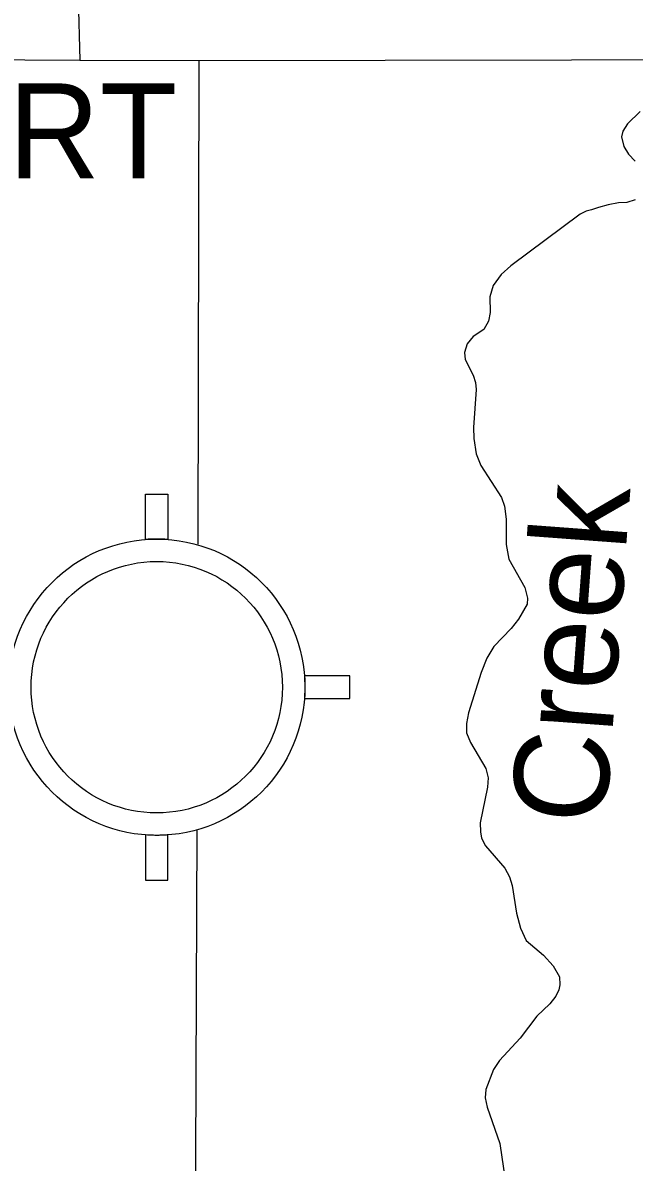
# Model space of a CAD drawing. Extents: x 1377389 to 1380723, y 1168351 to 1170484.
# Drawn here: x 1378669.2 to 1378723.7, y 1169222.9 to 1169324.4 of the extents above; entities that cross this region are included whole.
import ezdxf

# ---------------------------------------------------------------- set-up
doc = ezdxf.new("R2010")
doc.units = 0
doc.layers.add('B_Fill', color=7, linetype='Continuous')

msp = doc.modelspace()

# ---------------------------------------------------------------- linework, layer by layer
at = {"layer": 'B_Fill'}
for p, q in [((1378680.12, 1169278.37), (1378680.12, 1169282.41)), ((1378680.12, 1169282.41), (1378682.12, 1169282.41)), ((1378698.32, 1169266.21), (1378694.28, 1169266.21)), ((1378698.32, 1169264.21), (1378698.32, 1169266.21)), ((1378682.12, 1169248.01), (1378682.12, 1169252.05)), ((1378680.12, 1169248.01), (1378682.12, 1169248.01))]:
    msp.add_line(p, q, dxfattribs=at)
for points in [[(1378673.68, 1169343.19), (1378674.25, 1169321.07)], [(1378580.97, 1169321.62), (1378674.25, 1169321.07), (1378684.86, 1169321.03), (1378718.08, 1169321.08)], [(1378684.86, 1169321.03), (1378684.77, 1169277.94)], [(1378718.08, 1169321.08), (1378766.19, 1169321.15)], [(1378724.21, 1169316.49), (1378723.08, 1169315.4), (1378722.67, 1169314.75), (1378722.54, 1169314.23), (1378722.76, 1169313.37), (1378723.16, 1169312.7), (1378723.75, 1169312.06)], [(1378723.77, 1169308.61), (1378723.01, 1169308.38), (1378722.27, 1169308.34), (1378721.35, 1169308.18), (1378720.49, 1169307.95), (1378719.86, 1169307.74), (1378719.38, 1169307.62), (1378718.86, 1169307.33)], [(1378718.86, 1169307.33), (1378712.68, 1169302.74), (1378711.8, 1169301.98), (1378711.09, 1169300.98), (1378710.81, 1169299.98), (1378710.82, 1169298.58), (1378710.68, 1169297.81), (1378710.26, 1169297.08), (1378709.31, 1169296.44), (1378708.77, 1169295.79), (1378708.55, 1169295.02), (1378708.62, 1169294.4), (1378709.31, 1169293), (1378709.52, 1169292.36), (1378709.6, 1169291.72), (1378709.35, 1169288.35), (1378709.38, 1169287.35), (1378709.59, 1169286)], [(1378709.59, 1169286), (1378709.99, 1169284.97), (1378711.85, 1169282.12), (1378712.11, 1169281.33), (1378712.27, 1169280.19), (1378712.26, 1169277.93), (1378712.51, 1169276.62), (1378713.93, 1169274.08), (1378714.15, 1169273.15), (1378714.12, 1169272.61), (1378713.35, 1169271.27), (1378712.71, 1169270.45), (1378711.17, 1169268.84), (1378710.53, 1169267.8), (1378710.02, 1169266.53), (1378708.89, 1169262.94), (1378708.71, 1169261.98), (1378708.73, 1169261.16), (1378709.09, 1169260.29), (1378710.46, 1169257.97), (1378710.65, 1169257.14), (1378710.61, 1169256.32), (1378709.95, 1169253.12), (1378709.96, 1169252.32), (1378710.06, 1169251.76), (1378710.43, 1169251.09), (1378712.13, 1169249.08), (1378712.57, 1169248.33), (1378712.8, 1169247.56), (1378713.18, 1169245.08), (1378713.55, 1169243.75), (1378714.03, 1169242.66), (1378715.58, 1169241.33), (1378716.46, 1169240.39), (1378717, 1169239.42), (1378717.05, 1169238.7), (1378716.96, 1169238.26), (1378716.68, 1169237.7), (1378716.14, 1169237), (1378715, 1169235.92), (1378713.51, 1169233.94), (1378711.68, 1169231.96), (1378711.14, 1169231.15), (1378710.44, 1169229.37), (1378710.38, 1169228.65), (1378710.57, 1169227.81), (1378711.7, 1169224.57), (1378712.34, 1169220.12)], [(1378682.12, 1169282.41), (1378682.12, 1169278.37), (1378681.98, 1169278.38), (1378681.84, 1169278.39), (1378681.71, 1169278.4), (1378681.54, 1169278.41), (1378681.39, 1169278.41), (1378681.21, 1169278.41), (1378681.09, 1169278.41), (1378680.93, 1169278.41), (1378680.77, 1169278.41), (1378680.63, 1169278.4), (1378680.47, 1169278.4), (1378680.34, 1169278.39), (1378680.23, 1169278.38), (1378680.12, 1169278.37)], [(1378694.28, 1169266.21), (1378694.28, 1169266.16), (1378694.29, 1169266.1), (1378694.29, 1169266.05), (1378694.29, 1169265.99), (1378694.3, 1169265.93), (1378694.3, 1169265.87), (1378694.3, 1169265.8), (1378694.3, 1169265.75), (1378694.31, 1169265.67), (1378694.31, 1169265.62), (1378694.31, 1169265.55), (1378694.31, 1169265.48), (1378694.31, 1169265.42), (1378694.31, 1169265.36), (1378694.31, 1169265.28), (1378694.32, 1169265.22), (1378694.31, 1169265.14), (1378694.31, 1169265.06), (1378694.31, 1169264.98), (1378694.31, 1169264.87), (1378694.31, 1169264.77), (1378694.31, 1169264.7), (1378694.3, 1169264.62), (1378694.3, 1169264.53), (1378694.29, 1169264.41), (1378694.29, 1169264.32), (1378694.28, 1169264.21), (1378698.32, 1169264.21)], [(1378684.69, 1169252.51), (1378684.26, 1169150.09)], [(1378682.12, 1169252.05), (1378682.05, 1169252.05), (1378681.96, 1169252.04), (1378681.86, 1169252.03), (1378681.73, 1169252.03), (1378681.62, 1169252.02), (1378681.5, 1169252.02), (1378681.39, 1169252.02), (1378681.29, 1169252.01), (1378681.14, 1169252.01), (1378680.96, 1169252.01), (1378680.82, 1169252.02), (1378680.67, 1169252.02), (1378680.55, 1169252.02), (1378680.39, 1169252.03), (1378680.28, 1169252.04), (1378680.12, 1169252.05), (1378680.12, 1169248.01)]]:
    msp.add_lwpolyline(points, dxfattribs=at)
for radius in [13.2, 11.2]:
    msp.add_circle((1378681.12, 1169265.21), radius, dxfattribs=at)

# ---------------------------------------------------------------- texts
msp.add_text('AIRPORT', height=8.448, dxfattribs=at).set_placement((1378632.73, 1169310.54))
msp.add_text('Creek', height=8.448, rotation=85.7608, dxfattribs=at).set_placement((1378721.11, 1169252.85))

doc.saveas('drawing.dxf')
